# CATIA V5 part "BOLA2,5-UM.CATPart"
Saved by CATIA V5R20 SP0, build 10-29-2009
Part number: BOLA2,5-UM
Revision: ANY
Definition: UNKNOWN
Nomenclature: BOLA2,5-UM
Source: Unknown
Bounding box of the stored display mesh (mm): x -1.25 to 1.25, y -1.25 to 1.25, z -1.25 to 1.25
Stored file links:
  C:\Users\Utente\Desktop\IO LAVORO\3D X SITO CF\X SITO\3D files UM\UM064242 PRODUCT\BOLA2,5-UM.CATPart
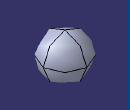
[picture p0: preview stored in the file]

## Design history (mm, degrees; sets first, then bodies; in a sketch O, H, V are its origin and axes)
Body1 "Revolución6" (main body)
  Solid1: solid without history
